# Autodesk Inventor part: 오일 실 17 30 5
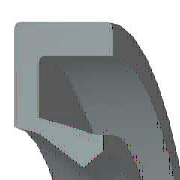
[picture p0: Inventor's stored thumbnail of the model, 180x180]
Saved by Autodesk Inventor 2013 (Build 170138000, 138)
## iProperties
IsCustomPart: 1
Created: 2012-02
Part Number: 오일 실 17 30 5
Material: 고무
Description: 오일 실 - 비스프링, 조립 GA
Document SubType Name: Modeling
Standard: JIS B 2402
Designer: mduedu
Standards Organization: JIS
Language: ko-KR
Size Designation: 17 30 5 A
Categories: <MemberInstance><Categories><Category DisplayName="샤프트 부품" InternalName="7f7aeb1f-a693-4053-b835-cee3144e0d98" Mnemonic="SHFT"><Category DisplayName="실링" Intern
Density: 0.93 g/cm^3
Author: mduedu
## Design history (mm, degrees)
body "Solid1"
revolve "회전1" stored, may be unused: angle "d27" = 360 deg
fillet "모깎기1" dims "d28" = 0.25 (= 0.05 x b)
sketch "스케치2"
  geometry: L1 (10.636, -3.75)-(11.286, -5); L2 (9.769, -3.438)-(10.636, -3.75); L3 (8.5, -1.375)-(9.769, -3.438); L4 (9.5, -0.75)-(8.5, -1.375); L5 (12.4, -4.375)-(9.5, -0.75); L6 (12.4, -0.25)-(12.4, -4.375); L7 (13.7, -0.25)-(12.4, -0.25); L8 (13.7, 0)-(13.7, -0.25); L9 (15, 0)-(13.7, 0); L10 (15, -5)-(15, 0); L11 (11.286, -5)-(15, -5); L12 (0, -9.6)-(0, 1.6) reference; L13 (28, 0)-(14, 0) reference
  constraints: 22 end point, 3 horizontal, 3 vertical
  dimensions: "d2" = 5 distance of L10.start L9.start (= b); "d4" = 1.3 distance of L9.start L8.start (= 0.1 x dd - 0.1 x Diam); "d6" = 0.25 distance of L8.start L7.start (= 0.05 x b); "d8" = 1 horizontal distance of L4.start L3.start (= 0.0769231 x dd - 0.0769231 x Diam); "d10" = 0.625 vertical distance of L5.start L10.start (= 0.125 x b); "d12" = 1.3 distance of L7.start L6.start (= 0.1 x dd - 0.1 x Diam); "d14" = 0.5 vertical distance of L4.start L6.start (= 0.1 x b); "d16" = 3.71429 distance of L1.end L10.start (= 0.285714 x dd - 0.285714 x Diam); "d18" = 0.65 horizontal distance of L1.start L1.end (= 0.05 x dd - 0.05 x Diam); "d20" = 0.625 vertical distance of L4.start L3.start (= 0.125 x b); "d22" = 1.25 vertical distance of L1.start L1.end (= 0.25 x b); "d24" = 0.86667 horizontal distance of L2.start L1.start (= 0.0666667 x dd - 0.0666667 x Diam); "d26" = 0.3125 vertical distance of L2.start L1.start (= 0.0625 x b); "d29" = 0 distance between parallel lines of L13 L9; "d30" = 8.5 distance from line of L3.start L12 (= 0.5 x Diam); "d31" = 15 distance between parallel lines of L12 L10 (= 0.5 x dd)
other parameters: "Diam" = 17 [user parameter; used in 7 equation terms], "b" = 5 [user parameter; used in 8 equation terms], "d1" = 8 (derived), "d3" = 2 (derived), "d5" = 0.4 (derived), "d7" = 1.53846 (derived), "d9" = 1 (derived), "d11" = 2 (derived), "d13" = 0.8 (derived), "d15" = 5.71429 (derived), "d17" = 1 (derived), "d19" = 1 (derived), "d21" = 2 (derived), "d23" = 1.33333 (derived), "d25" = 0.5 (derived), "d32" = 0
